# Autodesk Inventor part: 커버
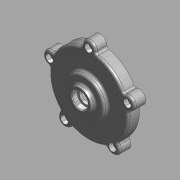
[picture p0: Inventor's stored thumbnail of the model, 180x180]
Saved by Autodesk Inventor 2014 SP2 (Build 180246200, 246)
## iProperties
Created: 2015-11
Part Number: 커버
Document SubType Name: 모델링
Designer: mdu
Material: 알루미늄 6061
Density: 2.71 g/cm^3
Appearance: 알루미늄 캐스트
Mass: 201.189 g
Surface Area: 286.328 cm^2
Volume: 74.2394 cm^3
변환 표준: STEP AP214IS
파일 이름: C:\Users\SeoGD\Desktop\?쒗뿕\而ㅻ쾭-1.stp
전처리기: Build: 253, Release: 2010 SP1 - Date: Wed 07/29/2009
전송 단위: 밀리미터
불확실성: 0.01
Author: mdu
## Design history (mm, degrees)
sketch "스케치1"
  geometry: L1 (0, 0)-(0, 26); L2 (50, 0)-(50, 15); L3 (50, 15)-(25, 15); L4 (25, 15)-(25, 21); L5 (25, 21)-(15, 21); L6 (15, 21)-(13.66, 26); L7 (13.66, 26)-(10, 26); L8 (50, 0)-(45, 0); L9 (45, 0)-(45, 10); L10 (45, 10)-(14.5, 10); L11 (14.5, 10)-(13.266, 3); L12 (13.266, 3)-(11, 3); L13 (11, 3)-(11, 16); L14 (11, 16)-(7.5, 16); L15 (7.5, 16)-(7.5, 19); L16 (7.5, 19)-(10, 19); L17 (10, 19)-(10, 26)
  constraints: 34 end point, 10 parallel, 2 perpendicular, 2 point on line, 1 vertical
  dimensions: "d11" = 100 diameter of L2 L1; "d12" = 22 diameter of L13 L1; "d13" = 90 diameter of L9 L1; "d14" = 15 distance between parallel lines of L3 L8; "d15" = 10 distance between parallel lines of L8 L10; "d16" = 29 diameter of L10.end L1; "d17" = 100 deg angle of L11 L10; "d18" = 7 distance between parallel lines of L12 L10; "d19" = 13 distance between parallel lines of L14 L12; "d20" = 3 distance between parallel lines of L16 L14; "d21" = 15 diameter of L15 L1; "d22" = 20 diameter of L17 L1; "d23" = 30 diameter of L5.end L1; "d24" = 6 distance between parallel lines of L5 L3; "d25" = 50 diameter of L4 L1; "d26" = 105 deg angle of L5 L6; "d50" = 26 distance of L1.start L1.end
revolve "회전1" sketch "스케치1" stored, may be unused: angle "d27" = 90 deg
sketch "스케치2" dims "d29" = 104
  geometry: A1 r 8.5 centre (0, 52) between (8.074, 49.344) and (-8.074, 49.344); A2 r 50 centre (0, 0) between (-8.074, 49.344) and (8.074, 49.344) reference; 2 further points
  constraints: 4 point on circle, 2 vertical alignment, 1 centre point, 1 coincident, 2 other
  dimensions: "d28" = 17 diameter of A1
extrude "돌출1" join sketch "스케치2" stored distance "d30" = 10; taper "d31" = 0 deg
fillet "모깎기3" dims "d32" = 3
fillet "모깎기4" dims "d45" = 3, "d46" = 0.2
chamfer "모따기1" distance "d47" = 1; stored, may be unused: second distance "d48" = 2, angle "d49" = 45 deg
hole "구멍2" diameter "d38" = 5.5; stored, may be unused: countersink angle "d42" = 90 deg, drill point angle "d44" = 118 deg; dims "d36" = 10, "d37" = 10, "d39" = 6, "d40" = 9.5, "d41" = 5.4, "d43" = 8
node "솔리드1"
node "솔리드 본체"
node "곡면 본체"
pattern_circular "원형 패턴1" dims angle "d34" = 360 deg
pattern_circular "원형 패턴2" dims angle "d52" = 360 deg
node "솔리드2"
